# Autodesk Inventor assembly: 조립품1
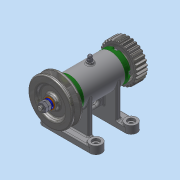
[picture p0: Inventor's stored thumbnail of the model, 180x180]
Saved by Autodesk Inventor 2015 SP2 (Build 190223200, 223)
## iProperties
Created: 2015-11
Part Number: 조립품1
Document SubType Name: Assembly
Designer: AMC
Author: AMC
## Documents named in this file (16)
- C:\Users\AMC\Desktop\451109V1006\조립품1.iam
- C:\Users\AMC\Desktop\451109V1006\부품1.ipt
- C:\Users\AMC\Desktop\451109V1006\축.ipt
- C:\Users\AMC\Desktop\451109V1006\베어링 15 x 32 x 9.ipt
- C:\Users\AMC\Desktop\451109V1006\커버.ipt
- C:\Users\AMC\Desktop\451109V1006\오일 실 15 25 7.ipt
- C:\Users\AMC\Desktop\451109V1006\볼트 M4 x 12.ipt
- C:\Users\AMC\Desktop\451109V1006\키 3 x 3 x 12.ipt
- C:\Users\AMC\Desktop\451109V1006\V벨트풀리.ipt
- C:\Users\AMC\Desktop\451109V1006\스퍼기어.ipt
- C:\Users\AMC\Desktop\451109V1006\와셔 8x17.ipt
- C:\Users\AMC\Desktop\451109V1006\스프링와셔 8.ipt
- C:\Users\AMC\Desktop\451109V1006\너트 M 8.ipt
- C:\Users\AMC\Desktop\451109V1006\와셔 6x11.5.ipt
- C:\Users\AMC\Desktop\451109V1006\니플 M 6 x 0.75.ipt
- C:\Users\AMC\Desktop\451109V1006\볼트 M 6 x 8.ipt
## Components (11 placed, 3 different names)
1. KS B 2023 6002 - 15 x 32 x 9:1
2. KS B 2023 6002 - 15 x 32 x 9:2
3. ISO 4762 M4 x 12:1
4. ISO 4762 M4 x 12:2
5. ISO 4762 M4 x 12:3
6. ISO 4762 M4 x 12:4
7. ISO 4762 M4 x 12:5
8. ISO 4762 M4 x 12:6
9. ISO 4762 M4 x 12:7
10. ISO 4762 M4 x 12:8
11. V벨트풀리:1
